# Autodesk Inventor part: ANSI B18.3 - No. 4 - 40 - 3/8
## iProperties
Comments: To add or edit properties for Autodesk Inventor files, use iProperties.
Created: 2004-06
Part Number: ANSI B18.3 - No. 4 - 40 - 3/8
Vendor: Autodesk Inc.
Document SubType Name: Modeling
Designer: jpittman
Material: Default
Description: Hexagon Socket Head Cap Screw
Standard: ANSI B18.3
Alert: To add or edit properties for Autodesk Inventor files, use iProperties.
Control State: 0
Master: False
Checked Out: False
Shininess: 64.0
Length Units: 11272
Angle Units: 11279
Time Units: 11290
Mass Units: 11286
Length Display Precision: 3
Angle Display Precision: 2
Compacted: True
EGR: 3
Classification: un/spsc 31161501
Density: 0.0
Volumn: 0.0
Area: 0.0
PropertySet Name: Model Information
Author: jpittman
Revision Number: 8
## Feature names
1. Body [Revolution]
2. Slot [Extrusion]
3. Fillet1
4. Chamfer1
